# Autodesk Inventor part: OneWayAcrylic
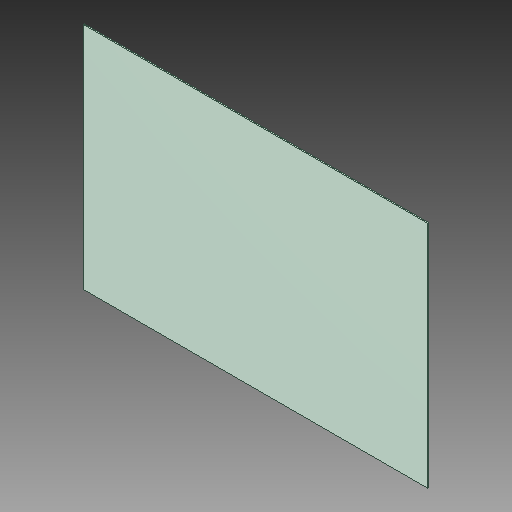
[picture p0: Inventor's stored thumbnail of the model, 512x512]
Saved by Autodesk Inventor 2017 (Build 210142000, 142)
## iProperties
Created: 2017-05
Part Number: OneWayAcrylic
Material: Generic
Document SubType Name: Modeling
Designer: Savy
Density: 1 g/cm^3
Appearance: Default
Mass: 1672.25 g
Surface Area: 11239.8 cm^2
Volume: 1672.25 cm^3
Author: Savy
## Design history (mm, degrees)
feature "SOLID1"
body "Solid1"
